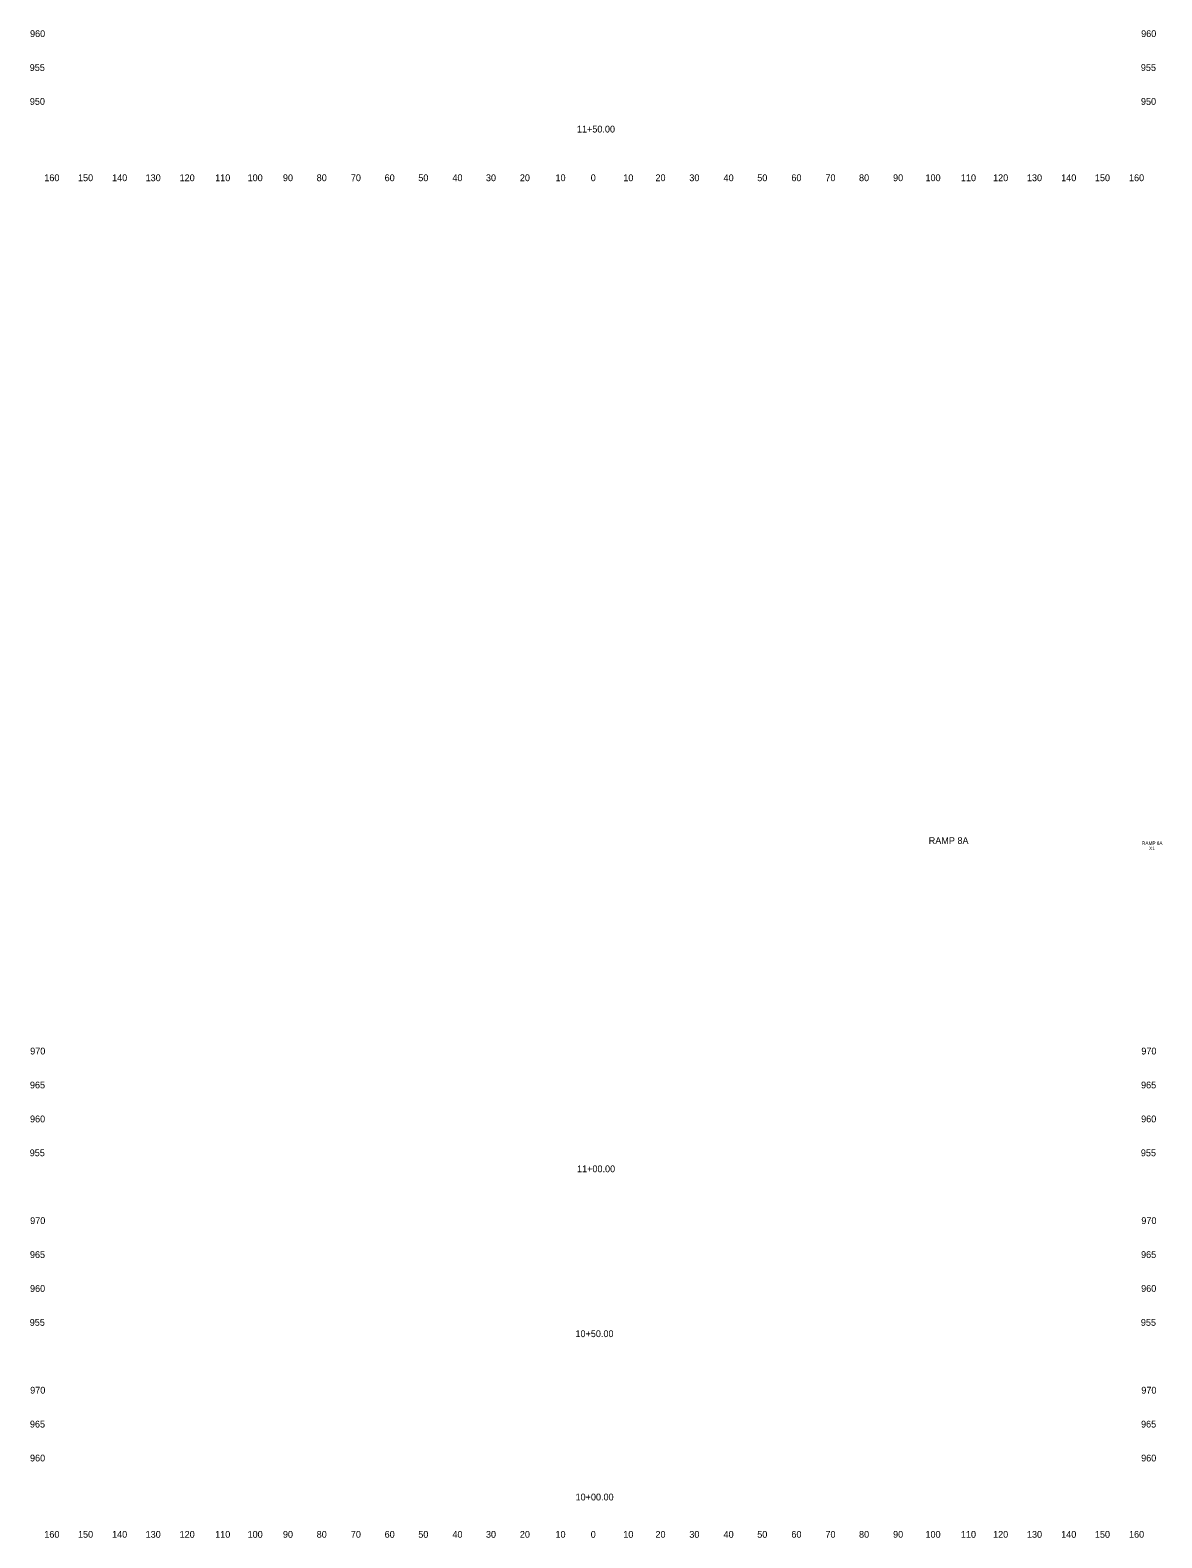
# Model space of a CAD drawing. Extents: x 4994 to 5328, y 4997 to 8804.
# Drawn here: x 4993.9 to 5327.8, y 4997.5 to 5442 of the extents above; entities that cross this region are included whole.
import ezdxf

# ---------------------------------------------------------------- set-up
doc = ezdxf.new("R2010")
doc.units = 0
for name, color, linetype in [('RD_SHT_ID', 7, 'Continuous'), ('RD_XS_TX_Offset', 7, 'Continuous'), ('RD_XS_TX_Station', 7, 'Continuous')]:
    doc.layers.add(name, color=color, linetype=linetype)

msp = doc.modelspace()

# ---------------------------------------------------------------- texts
at = {"layer": 'RD_SHT_ID'}
for s, height, p in [('RAMP 8A', 2, (5259.02, 5202.06)), ('RAMP 8A', 1, (5321.93, 5201.8)), ('X1', 1, (5324.02, 5200.3))]:
    msp.add_text(s, height=height, dxfattribs=at).set_placement(p)
at = {"layer": 'RD_XS_TX_Offset'}
for s, p in [('960', (4993.89, 5440)), ('960', (5321.69, 5440)), ('955', (4993.8, 5430)), ('955', (5321.6, 5430)), ('950', (4993.83, 5420)), ('950', (5321.63, 5420)), ('160', (4998.1, 5397.5)), ('150', (5008.04, 5397.5)), ('140', (5018.1, 5397.5)), ('130', (5027.99, 5397.5)), ('120', (5038.01, 5397.5)), ('110', (5048.51, 5397.5)), ('100', (5058.07, 5397.5)), ('90', (5068.5, 5397.5)), ('80', (5078.46, 5397.5)), ('70', (5088.54, 5397.5)), ('60', (5098.5, 5397.5)), ('50', (5108.43, 5397.5)), ('40', (5118.5, 5397.5)), ('30', (5128.39, 5397.5)), ('20', (5138.4, 5397.5)), ('10', (5148.91, 5397.5)), ('0', (5159.3, 5397.5)), ('0', (5159.3, 5397.5)), ('10', (5168.91, 5397.5)), ('20', (5178.4, 5397.5)), ('30', (5188.39, 5397.5)), ('40', (5198.5, 5397.5)), ('50', (5208.43, 5397.5)), ('60', (5218.5, 5397.5)), ('70', (5228.54, 5397.5)), ('80', (5238.46, 5397.5)), ('90', (5248.5, 5397.5)), ('100', (5258.07, 5397.5)), ('110', (5268.51, 5397.5)), ('120', (5278.01, 5397.5)), ('130', (5287.99, 5397.5)), ('140', (5298.1, 5397.5)), ('150', (5308.04, 5397.5)), ('160', (5318.1, 5397.5)), ('970', (4993.94, 5140)), ('970', (5321.74, 5140)), ('965', (4993.86, 5130)), ('965', (5321.66, 5130)), ('960', (4993.89, 5120)), ('960', (5321.69, 5120)), ('955', (4993.8, 5110)), ('955', (5321.6, 5110)), ('970', (4993.94, 5090)), ('970', (5321.74, 5090)), ('965', (4993.86, 5080)), ('965', (5321.66, 5080)), ('960', (4993.89, 5070)), ('960', (5321.69, 5070)), ('955', (4993.8, 5060)), ('955', (5321.6, 5060)), ('970', (4993.94, 5040)), ('970', (5321.74, 5040)), ('965', (4993.86, 5030)), ('965', (5321.66, 5030)), ('960', (4993.89, 5020)), ('960', (5321.69, 5020)), ('160', (4998.1, 4997.5)), ('150', (5008.04, 4997.5)), ('140', (5018.1, 4997.5)), ('130', (5027.99, 4997.5)), ('120', (5038.01, 4997.5)), ('110', (5048.51, 4997.5)), ('100', (5058.07, 4997.5)), ('90', (5068.5, 4997.5)), ('80', (5078.46, 4997.5)), ('70', (5088.54, 4997.5)), ('60', (5098.5, 4997.5)), ('50', (5108.43, 4997.5)), ('40', (5118.5, 4997.5)), ('30', (5128.39, 4997.5)), ('20', (5138.4, 4997.5)), ('10', (5148.91, 4997.5)), ('0', (5159.3, 4997.5)), ('0', (5159.3, 4997.5)), ('10', (5168.91, 4997.5)), ('20', (5178.4, 4997.5)), ('30', (5188.39, 4997.5)), ('40', (5198.5, 4997.5)), ('50', (5208.43, 4997.5)), ('60', (5218.5, 4997.5)), ('70', (5228.54, 4997.5)), ('80', (5238.46, 4997.5)), ('90', (5248.5, 4997.5)), ('100', (5258.07, 4997.5)), ('110', (5268.51, 4997.5)), ('120', (5278.01, 4997.5)), ('130', (5287.99, 4997.5)), ('140', (5298.1, 4997.5)), ('150', (5308.04, 4997.5)), ('160', (5318.1, 4997.5))]:
    msp.add_text(s, height=2, dxfattribs=at).set_placement(p)
at = {"layer": 'RD_XS_TX_Station'}
for s, p in [('11+50.00', (5155.24, 5411.85)), ('11+00.00', (5155.27, 5105.28)), ('10+50.00', (5154.8, 5056.66)), ('10+00.00', (5154.83, 5008.5))]:
    msp.add_text(s, height=2, dxfattribs=at).set_placement(p)

doc.saveas('drawing.dxf')
